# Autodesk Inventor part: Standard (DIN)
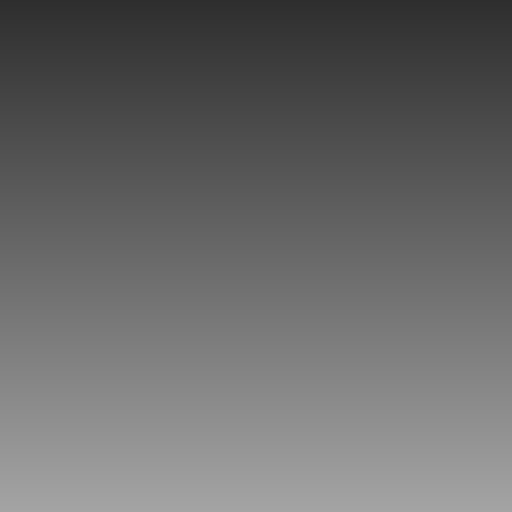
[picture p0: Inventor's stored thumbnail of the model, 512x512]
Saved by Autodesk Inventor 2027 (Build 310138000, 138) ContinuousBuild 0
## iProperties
Shininess: 64.0
Length Units: 11269
Angle Units: 11279
Time Units: 11290
Mass Units: 11283
Length Display Precision: 3
Angle Display Precision: 2
Compacted: True
Part Number: Standard (DIN)
Document SubType Name: Modeling
Created: 2002-07
Density: 1 g/cm^3
Material: Generic
Appearance: Default
Density: 0.0
Volumn: 0.0
Area: 0.0
PropertySet Name: Model Information
Control State: 0
Master: False
Checked Out: False
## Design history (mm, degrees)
